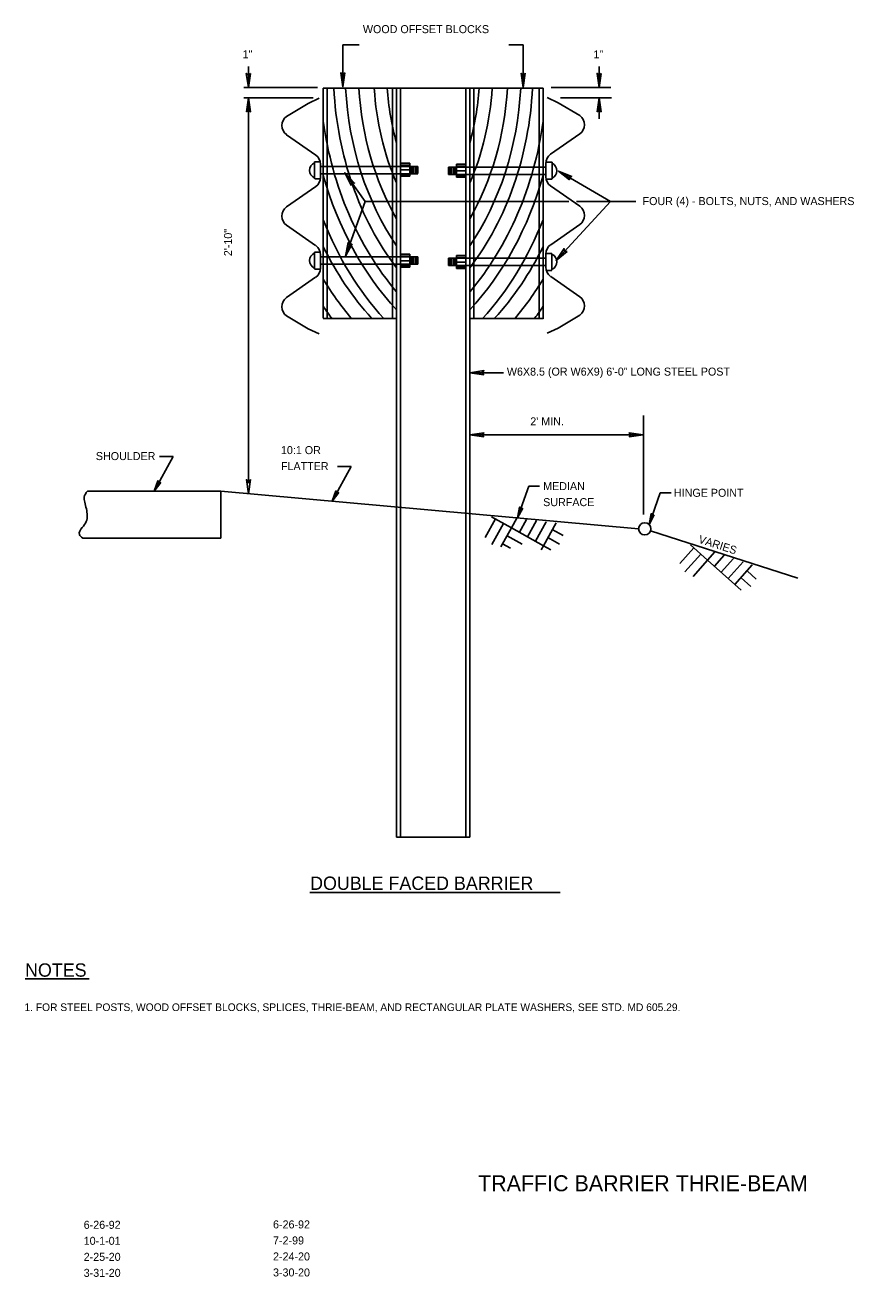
# Model space of a CAD drawing. Extents: x 12.66 to 18.87, y 6.01 to 15.4.
import ezdxf

# ---------------------------------------------------------------- set-up
doc = ezdxf.new("R2010")
doc.units = 0
for name, color, linetype in [('DETL-DIMS', 7, 'Continuous'), ('DETL-LINE', 7, 'Continuous'), ('DETL-NOTE', 7, 'Continuous'), ('DETL-PATT', 7, 'Continuous'), ('DETL-TITL', 7, 'Continuous'), ('TTLB-TEXT', 7, 'Continuous')]:
    doc.layers.add(name, color=color, linetype=linetype)

msp = doc.modelspace()

# ---------------------------------------------------------------- linework, layer by layer
at = {"layer": 'DETL-DIMS'}
for p, q in [((15.0439, 15.2475), (15.0439, 14.9327)), ((15.1646, 15.2475), (15.0439, 15.2475)), ((16.395, 15.2475), (16.2873, 15.2475)), ((16.395, 15.2475), (16.395, 14.9282)), ((14.3204, 15.0322), (14.3357, 14.9267)), ((14.3204, 15.0322), (14.3357, 15.019)), ((14.3357, 15.0841), (14.3357, 14.9267)), ((14.3511, 15.0322), (14.3357, 14.9267)), ((14.3511, 15.0322), (14.3357, 15.019)), ((15.0286, 15.0382), (15.0439, 14.9327)), ((15.0286, 15.0382), (15.0439, 15.025)), ((15.0593, 15.0382), (15.0439, 14.9327)), ((15.0593, 15.0382), (15.0439, 15.025)), ((16.3796, 15.0336), (16.395, 14.9282)), ((16.3796, 15.0336), (16.395, 15.0204)), ((16.4104, 15.0336), (16.395, 14.9282)), ((16.4104, 15.0336), (16.395, 15.0204)), ((16.9484, 15.0322), (16.9637, 14.9267)), ((16.9484, 15.0322), (16.9637, 15.019)), ((16.9637, 15.0841), (16.9637, 14.9267)), ((16.9791, 15.0322), (16.9637, 14.9267)), ((16.9791, 15.0322), (16.9637, 15.019)), ((14.853, 14.9267), (14.3018, 14.9267)), ((16.6046, 14.9267), (17.0511, 14.9267)), ((14.8218, 14.8505), (14.3018, 14.8505)), ((14.3214, 14.7451), (14.3368, 14.8505)), ((14.3522, 14.7451), (14.3368, 14.8505)), ((14.3368, 14.847), (14.3368, 11.9602)), ((16.6741, 14.8505), (17.0547, 14.8505)), ((16.9478, 14.7451), (16.9632, 14.8505)), ((16.9786, 14.7451), (16.9632, 14.8505)), ((16.9637, 14.8506), (16.9637, 14.6932)), ((14.3214, 14.7451), (14.3368, 14.7583)), ((14.3522, 14.7451), (14.3368, 14.7583)), ((16.9478, 14.7451), (16.9632, 14.7583)), ((16.9786, 14.7451), (16.9632, 14.7583)), ((15.2105, 14.0736), (15.0578, 14.288)), ((15.1315, 14.2111), (15.0578, 14.288)), ((15.1065, 14.1932), (15.0578, 14.288)), ((17.0474, 14.0736), (16.6592, 14.3011)), ((16.7579, 14.2611), (16.6592, 14.3011)), ((16.7424, 14.2345), (16.6592, 14.3011)), ((15.1065, 14.1932), (15.1113, 14.2129)), ((15.1315, 14.2111), (15.1113, 14.2129)), ((16.7579, 14.2611), (16.7387, 14.2545)), ((16.7424, 14.2345), (16.7387, 14.2545)), ((15.2105, 14.0736), (15.0624, 13.6618)), ((15.2105, 14.0736), (15.6975, 14.0736)), ((15.6975, 14.0736), (16.7375, 14.0736)), ((17.0474, 14.0736), (16.6407, 13.6311)), ((17.2387, 14.0736), (16.7932, 14.0736)), ((15.0836, 13.7662), (15.0624, 13.6618)), ((15.1126, 13.7558), (15.0624, 13.6618)), ((15.0836, 13.7662), (15.0936, 13.7486)), ((15.1126, 13.7558), (15.0936, 13.7486)), ((16.7007, 13.7191), (16.6407, 13.6311)), ((16.7007, 13.7191), (16.7031, 13.699)), ((16.7233, 13.6983), (16.6407, 13.6311)), ((16.7233, 13.6983), (16.7031, 13.699)), ((16.1001, 12.8048), (15.9946, 12.7895)), ((16.2467, 12.7895), (15.9946, 12.7895)), ((16.1001, 12.7741), (15.9946, 12.7895)), ((16.1001, 12.8048), (16.0869, 12.7895)), ((16.1001, 12.7741), (16.0869, 12.7895)), ((17.2955, 12.4675), (17.2955, 11.7265)), ((16.1001, 12.3384), (15.9946, 12.3231)), ((16.1001, 12.3077), (15.9946, 12.3231)), ((17.2937, 12.3231), (15.9946, 12.3231)), ((16.1001, 12.3384), (16.0869, 12.3231)), ((16.1001, 12.3077), (16.0869, 12.3231)), ((17.1882, 12.3384), (17.2937, 12.3231)), ((17.1882, 12.3384), (17.2014, 12.3231)), ((17.1882, 12.3077), (17.2937, 12.3231)), ((17.1882, 12.3077), (17.2014, 12.3231)), ((13.7713, 12.1619), (13.6295, 11.9008)), ((13.7713, 12.1619), (13.6709, 12.1619)), ((15.1049, 12.0868), (14.9632, 11.8256)), ((15.1049, 12.0868), (15.0045, 12.0868)), ((13.6583, 11.9788), (13.6295, 11.9008)), ((13.6794, 11.9674), (13.6295, 11.9008)), ((13.6583, 11.9788), (13.6639, 11.964)), ((13.6794, 11.9674), (13.6639, 11.964)), ((14.3214, 11.9875), (14.3368, 11.8821)), ((14.3214, 11.9875), (14.3368, 11.9743)), ((14.3522, 11.9875), (14.3368, 11.8821)), ((14.3522, 11.9875), (14.3368, 11.9743)), ((16.4357, 11.9383), (16.3519, 11.7005)), ((16.4357, 11.9383), (16.5171, 11.9383)), ((14.9919, 11.9037), (14.9632, 11.8256)), ((15.013, 11.8923), (14.9632, 11.8256)), ((14.9919, 11.9037), (14.9975, 11.8889)), ((15.013, 11.8923), (14.9975, 11.8889)), ((17.4216, 11.8889), (17.3379, 11.6511)), ((17.4216, 11.8889), (17.5031, 11.8889)), ((16.368, 11.7822), (16.3519, 11.7005)), ((16.3906, 11.7742), (16.3519, 11.7005)), ((16.368, 11.7822), (16.3758, 11.7684)), ((16.3906, 11.7742), (16.3758, 11.7684)), ((17.3539, 11.7327), (17.3379, 11.6511)), ((17.3539, 11.7327), (17.3618, 11.719)), ((17.3765, 11.7247), (17.3379, 11.6511)), ((17.3765, 11.7247), (17.3618, 11.719))]:
    msp.add_line(p, q, dxfattribs=at)
for points in [[(14.3511, 15.0322), (14.3357, 14.9267), (14.3204, 15.0322), (14.3357, 15.019)], [(15.0593, 15.0382), (15.0439, 14.9327), (15.0286, 15.0382), (15.0439, 15.025)], [(16.4104, 15.0336), (16.395, 14.9282), (16.3796, 15.0336), (16.395, 15.0204)], [(16.9791, 15.0322), (16.9637, 14.9267), (16.9484, 15.0322), (16.9637, 15.019)], [(14.3214, 14.7451), (14.3368, 14.8505), (14.3522, 14.7451), (14.3368, 14.7583)], [(16.9478, 14.7451), (16.9632, 14.8505), (16.9786, 14.7451), (16.9632, 14.7583)], [(15.1065, 14.1932), (15.0578, 14.288), (15.1315, 14.2111), (15.1113, 14.2129)], [(16.7424, 14.2345), (16.6592, 14.3011), (16.7579, 14.2611), (16.7387, 14.2545)], [(15.1126, 13.7558), (15.0624, 13.6618), (15.0836, 13.7662), (15.0936, 13.7486)], [(16.7233, 13.6983), (16.6407, 13.6311), (16.7007, 13.7191), (16.7031, 13.699)], [(16.1001, 12.7741), (15.9946, 12.7895), (16.1001, 12.8048), (16.0869, 12.7895)], [(16.1001, 12.3077), (15.9946, 12.3231), (16.1001, 12.3384), (16.0869, 12.3231)], [(17.1882, 12.3077), (17.2937, 12.3231), (17.1882, 12.3384), (17.2014, 12.3231)], [(13.6794, 11.9674), (13.6295, 11.9008), (13.6583, 11.9788), (13.6639, 11.964)], [(14.3522, 11.9875), (14.3368, 11.8821), (14.3214, 11.9875), (14.3368, 11.9743)], [(15.013, 11.8923), (14.9632, 11.8256), (14.9919, 11.9037), (14.9975, 11.8889)], [(16.3906, 11.7742), (16.3519, 11.7005), (16.368, 11.7822), (16.3758, 11.7684)], [(17.3765, 11.7247), (17.3379, 11.6511), (17.3539, 11.7327), (17.3618, 11.719)]]:
    msp.add_lwpolyline(points, close=True, dxfattribs=at)
at = {"layer": 'DETL-LINE'}
for p, q in [((14.8968, 14.9225), (15.4457, 14.9225)), ((14.8968, 13.1977), (14.8968, 14.9225)), ((14.9273, 13.1936), (14.9273, 14.9225)), ((15.4152, 13.1957), (15.4152, 14.9225)), ((15.4457, 11.7673), (15.4457, 14.9225)), ((15.4457, 14.9225), (15.9946, 14.9225)), ((15.4762, 11.7794), (15.4762, 14.9225)), ((15.9641, 11.7274), (15.9641, 14.9225)), ((15.9946, 11.731), (15.9946, 14.9225)), ((15.9946, 14.9225), (16.5435, 14.9225)), ((16.0251, 13.1935), (16.0251, 14.9225)), ((16.5131, 13.1997), (16.5131, 14.9225)), ((16.5435, 13.1935), (16.5435, 14.9225)), ((14.7831, 14.8075), (14.8666, 14.8466)), ((16.657, 14.8132), (16.5735, 14.8523)), ((14.6218, 14.7105), (14.7831, 14.8075)), ((16.8184, 14.7161), (16.657, 14.8132)), ((14.8402, 14.4209), (14.6218, 14.5735)), ((16.5999, 14.4265), (16.8184, 14.5792)), ((14.8714, 14.3696), (14.8317, 14.3696)), ((14.8317, 14.3696), (14.8317, 14.2431)), ((15.4762, 14.3592), (15.5458, 14.3592)), ((15.5458, 14.3592), (15.5458, 14.2623)), ((16.5644, 14.3085), (16.5644, 14.3582)), ((16.5708, 14.3666), (16.6105, 14.3666)), ((16.6105, 14.3666), (16.6105, 14.2401)), ((14.8758, 14.3028), (14.8758, 14.3525)), ((14.8758, 14.3357), (15.5458, 14.3357)), ((14.8758, 14.2529), (14.8758, 14.3028)), ((14.8758, 14.2809), (15.5458, 14.2809)), ((15.5445, 14.3439), (15.4762, 14.3439)), ((15.5458, 14.3095), (15.4762, 14.3095)), ((15.5458, 14.2738), (15.4762, 14.2738)), ((15.5458, 14.3357), (15.6059, 14.3357)), ((15.5471, 14.2809), (15.6059, 14.2809)), ((15.6059, 14.3357), (15.6059, 14.2814)), ((15.8944, 14.3307), (15.8343, 14.3307)), ((15.8343, 14.3307), (15.8343, 14.2759)), ((15.8944, 14.2759), (15.8343, 14.2759)), ((15.964, 14.3528), (15.8944, 14.3528)), ((15.8944, 14.3528), (15.8944, 14.2558)), ((15.8944, 14.3374), (15.964, 14.3374)), ((16.5649, 14.3305), (15.8944, 14.3305)), ((15.8944, 14.303), (15.964, 14.303)), ((16.5637, 14.2757), (15.8944, 14.2757)), ((15.8944, 14.2674), (15.964, 14.2674)), ((16.5644, 14.2586), (16.5644, 14.3085)), ((14.6218, 14.0317), (14.8402, 14.1845)), ((14.8726, 14.2422), (14.833, 14.2422)), ((15.4762, 14.2623), (15.5458, 14.2623)), ((15.964, 14.2558), (15.8944, 14.2558)), ((16.5695, 14.2392), (16.6092, 14.2392)), ((16.8184, 14.0374), (16.5999, 14.1901)), ((14.8398, 13.742), (14.6215, 13.8947)), ((16.6004, 13.7476), (16.8186, 13.9004)), ((14.8707, 13.6937), (14.8311, 13.6937)), ((14.8311, 13.6937), (14.8311, 13.5672)), ((14.8762, 13.6243), (14.8762, 13.6741)), ((14.8762, 13.6579), (15.5456, 13.6579)), ((14.8762, 13.5745), (14.8762, 13.6243)), ((15.476, 13.6769), (15.5456, 13.6769)), ((15.5443, 13.6617), (15.476, 13.6617)), ((15.5456, 13.6273), (15.476, 13.6273)), ((15.5456, 13.6769), (15.5456, 13.5801)), ((15.5456, 13.6579), (15.6057, 13.6579)), ((15.6057, 13.6579), (15.6057, 13.6031)), ((15.8946, 13.6479), (15.8345, 13.6479)), ((15.8345, 13.6479), (15.8345, 13.5936)), ((15.9641, 13.667), (15.8946, 13.667)), ((15.8946, 13.667), (15.8946, 13.5701)), ((16.5639, 13.6481), (15.8946, 13.6481)), ((15.8946, 13.6173), (15.9641, 13.6173)), ((15.8958, 13.6517), (15.9641, 13.6517)), ((16.5639, 13.63), (16.5639, 13.6797)), ((16.5639, 13.5801), (16.5639, 13.63)), ((16.5705, 13.684), (16.6102, 13.684)), ((16.6102, 13.684), (16.6102, 13.5575)), ((14.872, 13.5663), (14.8323, 13.5663)), ((14.8762, 13.6031), (15.5469, 13.6031)), ((15.5456, 13.5915), (15.476, 13.5915)), ((15.476, 13.5801), (15.5443, 13.5801)), ((15.5469, 13.6031), (15.6057, 13.6031)), ((15.8933, 13.5931), (15.8345, 13.5931)), ((16.5639, 13.5933), (15.8933, 13.5933)), ((15.8946, 13.5816), (15.9641, 13.5816)), ((15.9641, 13.5701), (15.8958, 13.5701)), ((16.5693, 13.5566), (16.6089, 13.5566)), ((14.6215, 13.3525), (14.8398, 13.5053)), ((16.8186, 13.3581), (16.6004, 13.511)), ((14.7828, 13.1187), (14.6215, 13.2156)), ((14.8968, 13.1968), (15.4457, 13.1968)), ((15.9946, 13.1968), (16.5435, 13.1968)), ((16.6573, 13.1243), (16.8186, 13.2213)), ((14.8664, 13.0796), (14.7828, 13.1187)), ((16.5738, 13.0852), (16.6573, 13.1243)), ((14.1291, 11.9008), (13.1299, 11.9008)), ((14.1291, 11.9008), (17.259, 11.6188)), ((14.1291, 11.9008), (14.1291, 11.5483)), ((15.4457, 9.3067), (15.4457, 11.7822)), ((15.4762, 9.3067), (15.4762, 11.7794)), ((15.9641, 9.3059), (15.9641, 11.7355)), ((15.9946, 9.3067), (15.9946, 11.7327)), ((13.095, 11.55), (13.0958, 11.5492)), ((13.0954, 11.5496), (13.0958, 11.5492)), ((14.1291, 11.5483), (13.0958, 11.5492)), ((17.3483, 11.6047), (18.4524, 11.2481)), ((15.4457, 9.3067), (15.9946, 9.3067))]:
    msp.add_line(p, q, dxfattribs=at)
msp.add_circle((17.3047, 11.6188), 0.0458, dxfattribs=at)
for centre, radius, start, end in [((14.6698, 14.6421), 0.0835, 125.01205, 234.98796), ((16.7703, 14.6477), 0.0835, 305.01203, 54.98794), ((14.857, 14.3059), 0.062, 115.30915, 244.69085), ((14.7922, 14.3525), 0.0835, 0.00001, 54.98796), ((16.6479, 14.3581), 0.0835, 125.01203, 179.99999), ((16.5852, 14.3029), 0.062, 295.30915, 64.69085), ((14.7922, 14.2529), 0.0835, 305.01205, 0.00001), ((16.6479, 14.2586), 0.0835, 179.99999, 234.98794), ((14.6698, 13.9632), 0.0835, 125.01205, 234.98796), ((16.7703, 13.9688), 0.0835, 305.01203, 54.98794), ((14.7921, 13.6737), 0.0835, 0.00001, 54.98796), ((16.648, 13.6794), 0.0835, 125.01203, 179.99999), ((14.8563, 13.63), 0.062, 115.30915, 244.69085), ((16.5849, 13.6203), 0.062, 295.30915, 64.69085), ((14.7921, 13.5737), 0.0835, 305.01205, 0.00001), ((16.648, 13.5793), 0.0835, 179.99999, 234.98794), ((14.6698, 13.2842), 0.0835, 125.01204, 234.98796), ((16.7703, 13.2899), 0.0835, 305.01204, 54.98795)]:
    msp.add_arc(centre, radius, start, end, dxfattribs=at)
msp.add_spline([(13.1299, 11.9008), (13.1059, 11.8575), (13.11, 11.8176), (13.1287, 11.7192), (13.1218, 11.6731), (13.091, 11.6288), (13.0701, 11.5765), (13.095, 11.55)], degree=3, dxfattribs=at)
at = {"layer": 'DETL-NOTE'}
msp.add_line((12.6631, 8.2447), (13.1431, 8.2447), dxfattribs=at)
at = {"layer": 'DETL-PATT'}
for p, q in [((15.5586, 14.3357), (15.5586, 14.2814)), ((15.5713, 14.3357), (15.5713, 14.2814)), ((15.5854, 14.3357), (15.5854, 14.2827)), ((15.5969, 14.3357), (15.5969, 14.2814)), ((15.8433, 14.3307), (15.8433, 14.2765)), ((15.8548, 14.3307), (15.8548, 14.2759)), ((15.8689, 14.3307), (15.8689, 14.2765)), ((15.8816, 14.3307), (15.8816, 14.2765)), ((15.5584, 13.6579), (15.5584, 13.6035)), ((15.5711, 13.6579), (15.5711, 13.6035)), ((15.5852, 13.6579), (15.5852, 13.6049)), ((15.5967, 13.6579), (15.5967, 13.6035)), ((15.8435, 13.6479), (15.8435, 13.5936)), ((15.855, 13.6479), (15.855, 13.5949)), ((15.869, 13.6479), (15.869, 13.5936)), ((15.8818, 13.6479), (15.8818, 13.5936)), ((16.1096, 11.5548), (16.1862, 11.6927)), ((16.3064, 11.626), (16.1571, 11.7088)), ((16.159, 11.5023), (16.2466, 11.6596)), ((16.3064, 11.626), (16.3465, 11.698)), ((16.3664, 11.5928), (16.42, 11.6898)), ((16.4263, 11.5597), (16.4938, 11.6812)), ((16.4863, 11.5262), (16.5677, 11.6726)), ((16.5461, 11.4927), (16.6409, 11.6643)), ((16.2268, 11.4829), (16.3064, 11.626)), ((16.3868, 11.503), (16.2734, 11.5661)), ((16.5461, 11.4927), (16.3064, 11.626)), ((16.667, 11.5046), (16.5798, 11.553)), ((16.6938, 11.5678), (16.6127, 11.6131)), ((16.2985, 11.4732), (16.2396, 11.5062)), ((16.5288, 11.4615), (16.5461, 11.4927)), ((16.6007, 11.4624), (16.5461, 11.4927)), ((17.5682, 11.3583), (17.6733, 11.476)), ((17.7758, 11.3844), (17.6485, 11.4981)), ((17.6047, 11.2963), (17.7249, 11.4303)), ((17.6666, 11.2624), (17.7758, 11.3844)), ((17.7758, 11.3844), (17.8309, 11.4458)), ((17.9802, 11.2014), (17.7758, 11.3844)), ((17.827, 11.3387), (17.9007, 11.4215)), ((17.8781, 11.2933), (17.9708, 11.3968)), ((17.9293, 11.2473), (18.041, 11.3721)), ((17.9802, 11.2014), (18.1106, 11.3479)), ((18.1408, 11.242), (18.0718, 11.3042)), ((18.0267, 11.1598), (17.9802, 11.2014)), ((18.1007, 11.1864), (18.0263, 11.2528))]:
    msp.add_line(p, q, dxfattribs=at)
for centre, major_axis, start_param, end_param in [((16.6896, 15.0543), (0, 2.1459), 1.632267, 2.331183), ((16.6896, 15.0543), (0, 2.0359), 1.635591, 2.272576), ((16.6896, 15.0543), (0, 1.9109), 1.639836, 2.191198), ((16.6896, 15.0543), (0, 1.7686), 1.645401, 2.067586), ((16.6896, 15.0543), (0, 1.6466), 1.650941, 1.906259), ((14.7507, 15.0543), (0, 1.6466), 4.376926, 4.632245), ((14.7507, 15.0543), (0, 1.7686), 4.215599, 4.637784), ((14.7507, 15.0543), (0, 1.9109), 4.091987, 4.64335), ((14.7507, 15.0543), (0, 2.0359), 4.01061, 4.647594), ((14.7507, 15.0543), (0, 2.1459), 3.952002, 4.650918), ((16.6896, 15.0543), (0, 2.2729), 1.738794, 2.388284), ((14.7507, 15.0543), (0, 2.2729), 3.894901, 4.544392), ((16.6896, 15.0543), (0, 2.3747), 1.907968, 2.427731), ((14.7507, 15.0543), (0, 2.3747), 3.855454, 4.375218), ((16.6026, 14.981), (0, 2.3747), 2.026551, 2.422933), ((14.8377, 14.981), (0, 2.3747), 3.861038, 4.256635), ((16.5133, 14.981), (0, 2.3747), 2.12388, 2.420246), ((14.927, 14.981), (0, 2.3747), 3.86233, 4.159306), ((16.4095, 14.9244), (0, 2.3735), 2.219847, 2.38493), ((15.0308, 14.9244), (0, 2.3735), 3.898457, 4.063338), ((16.354, 14.8089), (0, 2.3735), 2.266728, 2.319212), ((15.0863, 14.8089), (0, 2.3735), 3.967657, 4.016458)]:
    msp.add_ellipse(centre, major_axis=major_axis, ratio=0.8, start_param=start_param, end_param=end_param, dxfattribs=at)
at = {"layer": 'DETL-TITL'}
msp.add_line((14.7963, 8.894), (16.671, 8.894), dxfattribs=at)

# ---------------------------------------------------------------- texts
at = {"layer": 'DETL-LINE'}
msp.add_text('TRAFFIC BARRIER THRIE-BEAM', height=0.12, rotation=360, dxfattribs=at).set_placement((16.0569, 6.6535))
at = {"layer": 'DETL-NOTE'}
for s, height, p in [('WOOD OFFSET BLOCKS', 0.06, (15.1938, 15.3344)), ('1"', 0.06, (14.2927, 15.1459)), ('1"', 0.06, (16.9207, 15.1459)), ('FOUR (4) - BOLTS, NUTS, AND WASHERS', 0.06, (17.2887, 14.0457)), ('W6X8.5 (OR W6X9) 6\'-0" LONG STEEL POST', 0.06, (16.2722, 12.7675)), ("2' MIN.", 0.06, (16.4476, 12.3945)), ('10:1 OR', 0.06, (14.58, 12.179)), ('SHOULDER', 0.06, (13.1935, 12.1342)), ('FLATTER', 0.06, (14.58, 12.059)), ('MEDIAN', 0.06, (16.5441, 11.9091)), ('HINGE POINT', 0.06, (17.5237, 11.8591)), ('SURFACE', 0.06, (16.5441, 11.7891)), ('NOTES', 0.1, (12.6631, 8.2618)), ('1. FOR STEEL POSTS, WOOD OFFSET BLOCKS, SPLICES, THRIE-BEAM, AND RECTANGULAR PLATE WASHERS, SEE STD. MD 605.29.', 0.0574047, (12.6583, 8.0043))]:
    msp.add_text(s, height=height, dxfattribs=at).set_placement(p)
for s, rotation, p in [('2\'-10"', 90, (14.2135, 13.6628)), ('VARIES', 342.28516, (17.7026, 11.5158))]:
    msp.add_text(s, height=0.06, rotation=rotation, dxfattribs=at).set_placement(p)
at = {"layer": 'DETL-TITL'}
msp.add_text('DOUBLE FACED BARRIER  ', height=0.1, dxfattribs=at).set_placement((14.7984, 8.9126))
at = {"layer": 'TTLB-TEXT'}
for s, p in [('6-26-92', (13.1024, 6.372)), ('6-26-92', (14.5206, 6.375)), ('10-1-01', (13.1024, 6.252)), ('7-2-99', (14.5206, 6.255)), ('2-24-20', (14.5206, 6.135)), ('2-25-20', (13.1024, 6.132)), ('3-31-20', (13.1024, 6.012)), ('3-30-20', (14.5206, 6.015))]:
    msp.add_text(s, height=0.06, dxfattribs=at).set_placement(p)

doc.saveas('drawing.dxf')
